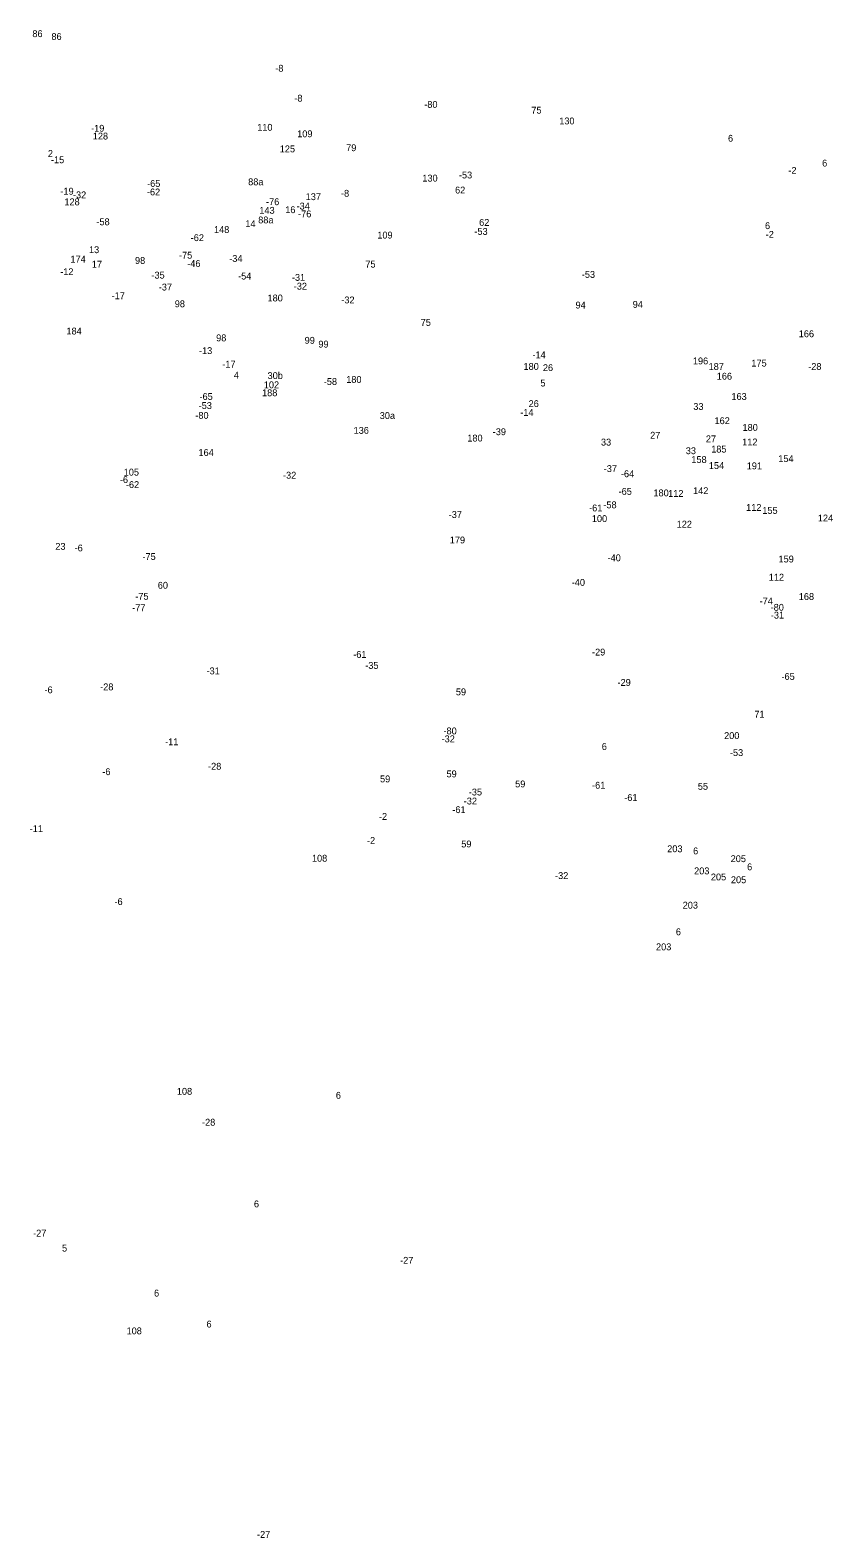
# Model space of a CAD drawing. Extents: x -664022 to -660357, y -995564 to -992665.
# Drawn here: x -662251 to -661783, y -994714 to -993834 of the extents above; entities that cross this region are included whole.
import ezdxf

# ---------------------------------------------------------------- set-up
doc = ezdxf.new("R2010")
doc.units = 0
doc.layers.add('Vrstva 24', color=7, linetype='Continuous')

msp = doc.modelspace()

# ---------------------------------------------------------------- texts
at = {"layer": 'Vrstva 24'}
for s, p in [('86', (-662250.124, -993837.8)), ('86', (-662238.994, -993839.48)), ('-8', (-662108.246, -993858)), ('-8', (-662097.116, -993875.47)), ('-80', (-662021.21, -993879.1)), ('75', (-661958.674, -993882.47)), ('130', (-661942.386, -993888.75)), ('-19', (-662215.815, -993893.02)), ('128', (-662214.842, -993897.56)), ('110', (-662118.81, -993892.47)), ('109', (-662095.452, -993896.25)), ('6', (-661843.824, -993898.86)), ('2', (-662241.088, -993907.74)), ('125', (-662105.632, -993905.06)), ('79', (-662066.849, -993904.38)), ('-15', (-662239.26, -993911.39)), ('6', (-661788.834, -993913.35)), ('-65', (-662183.121, -993925.25)), ('88a', (-662124.084, -993924.29)), ('130', (-662022.346, -993922.13)), ('-53', (-662000.996, -993920.3)), ('-2', (-661808.556, -993917.61)), ('-19', (-662233.755, -993929.78)), ('-32', (-662226.416, -993931.91)), ('-62', (-662183.221, -993930.2)), ('137', (-662090.488, -993932.96)), ('-8', (-662069.856, -993930.98)), ('62', (-662003.234, -993929.09)), ('128', (-662231.422, -993935.98)), ('143', (-662117.536, -993940.92)), ('-76', (-662113.646, -993935.9)), ('16', (-662102.428, -993940.57)), ('-34', (-662095.82, -993938.45)), ('-76', (-662094.926, -993943)), ('-58', (-662212.726, -993947.63)), ('14', (-662125.726, -993948.72)), ('88a', (-662118.214, -993946.55)), ('62', (-661989.174, -993947.99)), ('6', (-661822.204, -993949.88)), ('-62', (-662157.651, -993956.89)), ('148', (-662144.036, -993952.14)), ('109', (-662048.642, -993955.39)), ('-53', (-661991.946, -993953.23)), ('-2', (-661821.776, -993954.95)), ('174', (-662227.882, -993969.43)), ('13', (-662217.052, -993963.91)), ('-75', (-662164.482, -993967.13)), ('-34', (-662135.14, -993969.03)), ('-12', (-662233.87, -993976.75)), ('17', (-662215.388, -993972.36)), ('98', (-662190.184, -993970.19)), ('-46', (-662159.666, -993971.95)), ('75', (-662055.634, -993972.34)), ('-53', (-661929.206, -993978.33)), ('-35', (-662180.596, -993978.75)), ('-37', (-662176.292, -993985.71)), ('-54', (-662129.97, -993979.3)), ('-31', (-662098.55, -993980.05)), ('-32', (-662097.456, -993985.21)), ('-17', (-662203.865, -993990.8)), ('98', (-662166.964, -993995.49)), ('180', (-662112.786, -993992.09)), ('-32', (-662069.686, -993993.24)), ('94', (-661899.488, -993995.81)), ('94', (-661932.858, -993996.23)), ('184', (-662230.226, -994011.39)), ('75', (-662023.314, -994006.35)), ('166', (-661802.493, -994012.99)), ('98', (-662142.784, -994015.38)), ('99', (-662091.099, -994016.81)), ('99', (-662083.079, -994019.04)), ('-13', (-662152.8, -994022.83)), ('-17', (-662139.195, -994030.72)), ('-14', (-661958.024, -994025.28)), ('196', (-661864.323, -994028.83)), ('175', (-661830.158, -994030.11)), ('4', (-662132.462, -994037.16)), ('30b', (-662112.748, -994037.41)), ('180', (-662066.806, -994039.65)), ('180', (-661963.276, -994032.04)), ('26', (-661951.944, -994032.76)), ('187', (-661855.158, -994032.09)), ('166', (-661850.383, -994037.75)), ('-28', (-661796.966, -994032.09)), ('188', (-662115.972, -994047.43)), ('102', (-662114.946, -994042.79)), ('-58', (-662079.916, -994040.87)), ('5', (-661953.388, -994041.74)), ('5', (-661953.388, -994041.74)), ('-53', (-662153.006, -994054.89)), ('-65', (-662152.511, -994049.62)), ('26', (-661960.284, -994053.76)), ('33', (-661864.078, -994055.43)), ('163', (-661841.808, -994049.6)), ('-80', (-662154.94, -994060.62)), ('30a', (-662047.228, -994060.72)), ('-14', (-661965.124, -994058.9)), ('162', (-661851.688, -994063.73)), ('136', (-662062.508, -994069.37)), ('136', (-662062.508, -994069.37)), ('180', (-661996.086, -994073.87)), ('-39', (-661981.231, -994070.17)), ('27', (-661889.284, -994072.23)), ('27', (-661856.744, -994074.33)), ('180', (-661835.336, -994067.66)), ('164', (-662153.112, -994082.29)), ('33', (-661918.018, -994076.22)), ('33', (-661868.488, -994081.26)), ('185', (-661853.632, -994080.32)), ('112', (-661835.536, -994076.15)), ('-37', (-661916.402, -994091.71)), ('158', (-661865.212, -994086.41)), ('154', (-661855.016, -994089.91)), ('191', (-661832.882, -994090.1)), ('154', (-661814.456, -994085.87)), ('-6', (-662199.021, -994098.08)), ('105', (-662196.776, -994093.77)), ('-62', (-662195.501, -994101.04)), ('-32', (-662103.716, -994095.56)), ('-64', (-661906.376, -994094.71)), ('-65', (-661907.711, -994105)), ('180', (-661887.366, -994105.88)), ('112', (-661878.766, -994106.18)), ('142', (-661864.216, -994104.6)), ('-37', (-662006.952, -994118.49)), ('-61', (-661924.945, -994114.66)), ('-58', (-661916.616, -994112.86)), ('112', (-661833.226, -994114.37)), ('155', (-661823.772, -994116.13)), ('100', (-661923.34, -994120.87)), ('122', (-661873.802, -994124.14)), ('124', (-661791.336, -994120.54)), ('179', (-662006.323, -994133.36)), ('23', (-662236.718, -994137.08)), ('-6', (-662225.471, -994138.03)), ('-75', (-662185.842, -994143.01)), ('-40', (-661914.154, -994143.78)), ('159', (-661814.318, -994144.47)), ('60', (-662176.868, -994159.81)), ('-40', (-661935.074, -994158.11)), ('112', (-661819.996, -994155.1)), ('-75', (-662190.012, -994166.26)), ('-74', (-661825.366, -994169)), ('168', (-661802.478, -994166.4)), ('-77', (-662191.846, -994172.93)), ('-80', (-661818.91, -994172.67)), ('-31', (-661818.81, -994177.23)), ('-61', (-662062.715, -994200.16)), ('-35', (-662055.696, -994206.58)), ('-29', (-661923.231, -994198.8)), ('-31', (-662148.4, -994209.79)), ('-65', (-661812.591, -994213.03)), ('-6', (-662243.051, -994220.85)), ('-28', (-662210.526, -994219.13)), ('59', (-662002.774, -994222.02)), ('-29', (-661908.351, -994216.51)), ('71', (-661828.418, -994235.08)), ('-11', (-662172.594, -994251.16)), ('-32', (-662011.106, -994249.45)), ('-80', (-662009.99, -994244.83)), ('200', (-661846.096, -994247.55)), ('6', (-661917.544, -994253.92)), ('-53', (-661842.696, -994257.5)), ('-6', (-662209.271, -994268.63)), ('-28', (-662147.506, -994265.46)), ('59', (-662047.054, -994272.83)), ('59', (-662008.234, -994269.89)), ('59', (-661968.144, -994275.77)), ('-61', (-661923.215, -994276.52)), ('55', (-661861.448, -994277.17)), ('-32', (-661998.176, -994285.75)), ('-35', (-661995.226, -994280.49)), ('-61', (-661904.415, -994283.72)), ('-2', (-662047.706, -994294.76)), ('-61', (-662004.835, -994290.79)), ('-11', (-662251.674, -994301.86)), ('-2', (-662054.676, -994308.78)), ('59', (-661999.624, -994310.83)), ('108', (-662086.826, -994319.15)), ('203', (-661879.332, -994313.62)), ('6', (-661864.194, -994314.85)), ('205', (-661842.262, -994319.4)), ('-32', (-661944.826, -994329.28)), ('203', (-661863.612, -994326.52)), ('205', (-661853.822, -994330.08)), ('6', (-661832.654, -994324.17)), ('205', (-661842.112, -994331.71)), ('-6', (-662202.171, -994344.46)), ('203', (-661870.282, -994346.55)), ('6', (-661874.264, -994362.09)), ('203', (-661885.852, -994370.87)), ('108', (-662165.736, -994455.21)), ('6', (-662072.874, -994457.53)), ('-28', (-662151.026, -994473.25)), ('6', (-662120.724, -994520.94)), ('-27', (-662249.702, -994538.01)), ('5', (-662232.808, -994546.77)), ('-27', (-662035.332, -994553.87)), ('6', (-662179.074, -994573.01)), ('6', (-662148.424, -994591.07)), ('108', (-662195.126, -994595.06)), ('-27', (-662118.912, -994713.87))]:
    msp.add_text(s, height=4, dxfattribs=at).set_placement(p)

doc.saveas('drawing.dxf')
